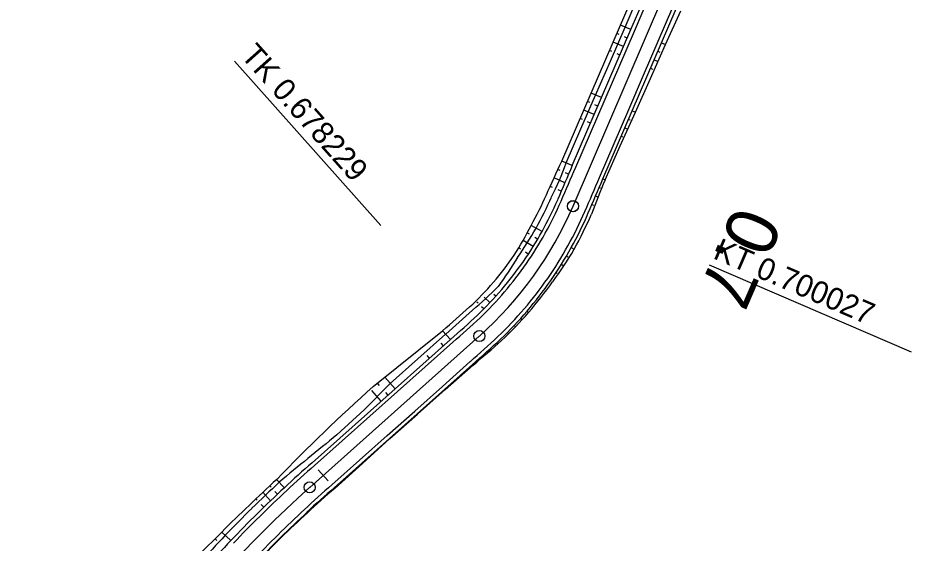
# Model space of a CAD drawing. Extents: x -481645 to -478728, y -1113199 to -1110710.
# Drawn here: x -480192.1 to -480071.5, y -1112507.2 to -1112436.3 of the extents above; entities that cross this region are included whole.
import ezdxf

# ---------------------------------------------------------------- set-up
doc = ezdxf.new("R2010")
doc.units = 0
for name, color, linetype in [('Vrstva 52', 7, 'Continuous'), ('Vrstva 53', 7, 'Continuous'), ('Vrstva 54', 7, 'Continuous'), ('Vrstva 55', 7, 'Continuous'), ('Vrstva 56', 7, 'Continuous'), ('Vrstva 57', 7, 'Continuous'), ('Vrstva 58', 7, 'Continuous'), ('Vrstva 59', 7, 'Continuous'), ('Vrstva 60', 7, 'Continuous'), ('Vrstva 61', 7, 'Continuous'), ('Vrstva 62', 7, 'Continuous')]:
    doc.layers.add(name, color=color, linetype=linetype)

msp = doc.modelspace()

# ---------------------------------------------------------------- linework, layer by layer
at = {"layer": 'Vrstva 52'}
for p, q in [((-480117.12, -1112461.7), (-480076.44, -1112367.31)), ((-480152.67, -1112499.65), (-480129.77, -1112479.24))]:
    msp.add_line(p, q, dxfattribs=at)
for centre, radius, start, end in [((-480163.03, -1112441.91), 50, 311.7077, 336.6864), ((-480052.87, -1112611.63), 150, 131.7077, 158.1186)]:
    msp.add_arc(centre, radius, start, end, dxfattribs=at)
at = {"layer": 'Vrstva 53'}
for p, q in [((-480110.71, -1112437.27), (-480108.72, -1112432.68)), ((-480104.62, -1112439.89), (-480102.58, -1112435.33)), ((-480112.69, -1112441.86), (-480110.71, -1112437.27)), ((-480106.66, -1112444.46), (-480104.62, -1112439.89)), ((-480114.68, -1112446.45), (-480112.69, -1112441.86)), ((-480108.7, -1112449.02), (-480106.66, -1112444.46)), ((-480116.66, -1112451.04), (-480114.68, -1112446.45)), ((-480110.75, -1112453.58), (-480108.7, -1112449.02)), ((-480118.65, -1112455.63), (-480116.66, -1112451.04)), ((-480112.8, -1112458.15), (-480110.75, -1112453.58)), ((-480144.1, -1112486.04), (-480134.74, -1112478.51)), ((-480134.36, -1112486.45), (-480130.61, -1112483.14)), ((-480138.11, -1112489.77), (-480134.36, -1112486.45)), ((-480149, -1112492.58), (-480145.3, -1112489.21)), ((-480141.85, -1112493.08), (-480138.11, -1112489.77)), ((-480145.56, -1112496.43), (-480141.85, -1112493.08)), ((-480149.26, -1112499.79), (-480145.56, -1112496.43))]:
    msp.add_line(p, q, dxfattribs=at)
for centre, radius, start, end in [((-485943.29, -1109801.96), 6400.66, 335.461603, 335.50635), ((-473992.43, -1114890.71), 6586.07, 158.324428, 158.367956), ((-480163, -1112441.84), 46.08, 330.828, 336.5575), ((-480163.1, -1112442.04), 52.71, 331.0858, 336.8154), ((-480163.9, -1112443.35), 46.16, 327.2716, 333.005), ((-480158.18, -1112445.91), 39.98, 312.6689, 325.9265), ((-480162.22, -1112440.65), 52.65, 323.5666, 329.2985), ((-480162.71, -1112441.49), 52.54, 318.8842, 324.6141), ((-480224.17, -1112372.54), 138.66, 310.1615, 312.1723), ((-480162.75, -1112441.61), 52.5, 313.2855, 319.0153), ((-480231.26, -1112362.09), 157.43, 309.7394, 311.5913), ((-479986.79, -1112662.6), 236.47, 131.7, 136.0823), ((-480053.4, -1112612.14), 153.8, 132.4085, 134.3184), ((-480102.14, -1112556.62), 73.83, 129.667, 133.5171), ((-480055.36, -1112614.11), 153.87, 133.2838, 135.1942), ((-480053.64, -1112612.36), 147.68, 132.2735, 134.1835), ((-480057.21, -1112616.17), 154.03, 134.1648, 136.0763), ((-480052.61, -1112611.37), 147.69, 134.7368, 136.6466)]:
    msp.add_arc(centre, radius, start, end, dxfattribs=at)
at = {"layer": 'Vrstva 54'}
for p, q in [((-480110.09, -1112437.53), (-480108.1, -1112432.95)), ((-480112.08, -1112442.12), (-480110.09, -1112437.53)), ((-480114.07, -1112446.71), (-480112.08, -1112442.12)), ((-480116.06, -1112451.29), (-480114.07, -1112446.71)), ((-480118.05, -1112455.88), (-480116.06, -1112451.29)), ((-480138.05, -1112482.31), (-480134.32, -1112478.99)), ((-480141.79, -1112485.63), (-480138.05, -1112482.31)), ((-480145.3, -1112489.21), (-480141.79, -1112485.63))]:
    msp.add_line(p, q, dxfattribs=at)
for centre, radius, start, end in [((-480146.02, -1112446.49), 29.5, 331.7223, 341.4402), ((-480162.99, -1112441.83), 46.83, 330.8136, 336.5432), ((-480162.99, -1112441.83), 46.82, 325.0838, 330.8134), ((-480164.95, -1112444.59), 46.98, 323.4712, 329.2149), ((-480160.56, -1112439.48), 46.97, 309.4939, 315.2392), ((-480226.32, -1112372.95), 140.39, 310.9473, 312.9416), ((-479873.28, -1112836.63), 440.9, 128.7078, 130.0156), ((-480053.08, -1112611.83), 153.27, 132.5743, 134.4842), ((-480053.07, -1112611.84), 153.28, 134.484, 136.3939), ((-480053.07, -1112611.84), 153.29, 136.3941, 138.3039)]:
    msp.add_arc(centre, radius, start, end, dxfattribs=at)
at = {"layer": 'Vrstva 55'}
for p, q in [((-480109.3, -1112437.88), (-480107.32, -1112433.28)), ((-480105.17, -1112439.66), (-480103.19, -1112435.06)), ((-480111.28, -1112442.47), (-480109.3, -1112437.88)), ((-480107.15, -1112444.25), (-480105.17, -1112439.66)), ((-480113.26, -1112447.06), (-480111.28, -1112442.47)), ((-480109.12, -1112448.84), (-480107.15, -1112444.25)), ((-480115.24, -1112451.65), (-480113.26, -1112447.06)), ((-480111.1, -1112453.43), (-480109.12, -1112448.84)), ((-480117.22, -1112456.24), (-480115.24, -1112451.65)), ((-480113.08, -1112458.02), (-480111.1, -1112453.43)), ((-480137.41, -1112483.03), (-480133.68, -1112479.71)), ((-480141.14, -1112486.36), (-480137.41, -1112483.03)), ((-480134.42, -1112486.39), (-480130.68, -1112483.07)), ((-480144.87, -1112489.69), (-480141.14, -1112486.36)), ((-480138.15, -1112489.72), (-480134.42, -1112486.39)), ((-480148.61, -1112493.01), (-480144.87, -1112489.69)), ((-480141.88, -1112493.05), (-480138.15, -1112489.72)), ((-480152.34, -1112496.34), (-480148.61, -1112493.01)), ((-480145.61, -1112496.37), (-480141.88, -1112493.05)), ((-480149.35, -1112499.7), (-480145.61, -1112496.37))]:
    msp.add_line(p, q, dxfattribs=at)
for centre, radius, start, end in [((-471553.39, -1116149.55), 9326.29, 156.670978, 156.701689), ((-520578.16, -1095022.28), 44061.64, 336.683075, 336.689578), ((-480163.03, -1112441.91), 47.75, 330.9256, 336.6551), ((-480163.03, -1112441.91), 52.25, 330.9256, 336.6551), ((-480163.03, -1112441.91), 47.75, 325.196, 330.9255), ((-480163.03, -1112441.91), 52.25, 325.196, 330.9256), ((-480163.03, -1112441.91), 47.75, 319.4664, 325.196), ((-480163.03, -1112441.91), 52.25, 319.4664, 325.196), ((-480163.03, -1112441.91), 47.75, 313.7368, 319.4664), ((-480227.79, -1112371.71), 143.25, 311.0724, 313.0404), ((-480163.03, -1112441.91), 52.25, 313.7368, 319.4664), ((-480233.83, -1112365.03), 156.75, 311.1489, 313.0057), ((-480103.35, -1112554.6), 76.12, 130.061, 133.8537), ((-480052.87, -1112611.63), 152.25, 132.6808, 134.5906), ((-480101.83, -1112556.27), 73.88, 130.0292, 133.8782), ((-480052.87, -1112611.63), 152.25, 134.5906, 136.5005), ((-480052.87, -1112611.63), 147.75, 132.6808, 134.5906), ((-480052.87, -1112611.63), 152.25, 136.5005, 138.4103), ((-480052.87, -1112611.63), 147.75, 134.5906, 136.5005)]:
    msp.add_arc(centre, radius, start, end, dxfattribs=at)
at = {"layer": 'Vrstva 56'}
for p, q in [((-480108.84, -1112438.07), (-480106.86, -1112433.48)), ((-480105.63, -1112439.46), (-480103.65, -1112434.87)), ((-480110.82, -1112442.67), (-480108.84, -1112438.07)), ((-480107.6, -1112444.05), (-480105.63, -1112439.46)), ((-480112.8, -1112447.26), (-480110.82, -1112442.67)), ((-480109.58, -1112448.64), (-480107.6, -1112444.05)), ((-480114.78, -1112451.85), (-480112.8, -1112447.26)), ((-480111.56, -1112453.23), (-480109.58, -1112448.64)), ((-480116.76, -1112456.44), (-480114.78, -1112451.85)), ((-480113.54, -1112457.82), (-480111.56, -1112453.23)), ((-480137.08, -1112483.41), (-480133.34, -1112480.08)), ((-480134.75, -1112486.02), (-480131.02, -1112482.69)), ((-480140.81, -1112486.73), (-480137.08, -1112483.41)), ((-480138.48, -1112489.35), (-480134.75, -1112486.02)), ((-480144.54, -1112490.06), (-480140.81, -1112486.73)), ((-480148.27, -1112493.39), (-480144.54, -1112490.06)), ((-480142.21, -1112492.67), (-480138.48, -1112489.35)), ((-480152.01, -1112496.71), (-480148.27, -1112493.39)), ((-480145.95, -1112496), (-480142.21, -1112492.67)), ((-480149.68, -1112499.33), (-480145.95, -1112496))]:
    msp.add_line(p, q, dxfattribs=at)
for centre, radius, start, end in [((-481062.27, -1112051.69), 1028.5, 336.54709, 336.82558), ((-481852.02, -1111711.35), 1891.96, 336.6106, 336.76205), ((-480163.03, -1112441.91), 48.25, 330.9256, 336.6551), ((-480163.03, -1112441.91), 51.75, 330.9256, 336.6551), ((-480163.03, -1112441.91), 48.25, 325.196, 330.9255), ((-480163.03, -1112441.91), 51.75, 325.196, 330.9256), ((-480163.03, -1112441.91), 48.25, 319.4664, 325.196), ((-480163.03, -1112441.91), 51.75, 319.4664, 325.196), ((-480163.03, -1112441.91), 48.25, 313.7368, 319.4664), ((-480163.03, -1112441.91), 51.75, 313.7368, 319.4664), ((-480228.46, -1112370.97), 144.75, 311.0815, 313.0361), ((-480233.16, -1112365.78), 155.25, 311.141, 313.0091), ((-480103.18, -1112554.79), 75.88, 130.0576, 133.8563), ((-480102, -1112556.08), 74.12, 130.0329, 133.8754), ((-480052.87, -1112611.63), 151.75, 132.6808, 134.5906), ((-480052.87, -1112611.63), 148.25, 132.6808, 134.5906), ((-480052.87, -1112611.63), 151.75, 134.5906, 136.5005), ((-480052.87, -1112611.63), 148.25, 134.5906, 136.5005)]:
    msp.add_arc(centre, radius, start, end, dxfattribs=at)
at = {"layer": 'Vrstva 57'}
for p, q in [((-480108.84, -1112438.07), (-480106.86, -1112433.48)), ((-480105.63, -1112439.46), (-480103.65, -1112434.87)), ((-480110.82, -1112442.67), (-480108.84, -1112438.07)), ((-480107.6, -1112444.05), (-480105.63, -1112439.46)), ((-480112.8, -1112447.26), (-480110.82, -1112442.67)), ((-480109.58, -1112448.64), (-480107.6, -1112444.05)), ((-480114.78, -1112451.85), (-480112.8, -1112447.26)), ((-480111.56, -1112453.23), (-480109.58, -1112448.64)), ((-480116.76, -1112456.44), (-480114.78, -1112451.85)), ((-480113.54, -1112457.82), (-480111.56, -1112453.23)), ((-480137.08, -1112483.41), (-480133.34, -1112480.08)), ((-480134.75, -1112486.02), (-480131.02, -1112482.69)), ((-480140.81, -1112486.73), (-480137.08, -1112483.41)), ((-480138.48, -1112489.35), (-480134.75, -1112486.02)), ((-480144.54, -1112490.06), (-480140.81, -1112486.73)), ((-480148.27, -1112493.39), (-480144.54, -1112490.06)), ((-480142.21, -1112492.67), (-480138.48, -1112489.35)), ((-480152.01, -1112496.71), (-480148.27, -1112493.39)), ((-480145.95, -1112496), (-480142.21, -1112492.67)), ((-480149.68, -1112499.33), (-480145.95, -1112496))]:
    msp.add_line(p, q, dxfattribs=at)
for centre, radius, start, end in [((-481062.27, -1112051.69), 1028.5, 336.54709, 336.82558), ((-481852.02, -1111711.35), 1891.96, 336.6106, 336.76205), ((-480163.03, -1112441.91), 48.25, 330.9256, 336.6551), ((-480163.03, -1112441.91), 51.75, 330.9256, 336.6551), ((-480163.03, -1112441.91), 48.25, 325.196, 330.9255), ((-480163.03, -1112441.91), 51.75, 325.196, 330.9256), ((-480163.03, -1112441.91), 48.25, 319.4664, 325.196), ((-480163.03, -1112441.91), 51.75, 319.4664, 325.196), ((-480163.03, -1112441.91), 48.25, 313.7368, 319.4664), ((-480163.03, -1112441.91), 51.75, 313.7368, 319.4664), ((-480228.46, -1112370.97), 144.75, 311.0815, 313.0361), ((-480233.16, -1112365.78), 155.25, 311.141, 313.0091), ((-480103.18, -1112554.79), 75.88, 130.0576, 133.8563), ((-480102, -1112556.08), 74.12, 130.0329, 133.8754), ((-480052.87, -1112611.63), 151.75, 132.6808, 134.5906), ((-480052.87, -1112611.63), 148.25, 132.6808, 134.5906), ((-480052.87, -1112611.63), 151.75, 134.5906, 136.5005), ((-480052.87, -1112611.63), 148.25, 134.5906, 136.5005)]:
    msp.add_arc(centre, radius, start, end, dxfattribs=at)
at = {"layer": 'Vrstva 58'}
msp.add_line((-480150.18, -1112498.77), (-480151.51, -1112497.27), dxfattribs=at)
at = {"layer": 'Vrstva 59'}
for p, q in [((-480162.84, -1112442.14), (-480143.08, -1112464.31)), ((-480098.75, -1112469.61), (-480071.48, -1112481.37))]:
    msp.add_line(p, q, dxfattribs=at)
for centre in [(-480117.12, -1112461.7), (-480129.77, -1112479.24), (-480152.67, -1112499.65)]:
    msp.add_circle(centre, 0.75, dxfattribs=at)
at = {"layer": 'Vrstva 60'}
msp.add_circle((-480117.13, -1112461.72), 0.75, dxfattribs=at)
at = {"layer": 'Vrstva 61'}
for p, q in [((-480109.3, -1112437.88), (-480110.71, -1112437.27)), ((-480110.9, -1112438.55), (-480111.2, -1112438.42)), ((-480109.79, -1112439.02), (-480110.19, -1112438.85)), ((-480110.29, -1112440.17), (-480111.7, -1112439.56)), ((-480111.89, -1112440.84), (-480112.2, -1112440.71)), ((-480110.78, -1112441.32), (-480111.18, -1112441.15)), ((-480113.26, -1112447.06), (-480114.68, -1112446.45)), ((-480114.87, -1112447.72), (-480115.17, -1112447.59)), ((-480114.25, -1112449.35), (-480115.67, -1112448.74)), ((-480113.75, -1112448.21), (-480114.16, -1112448.03)), ((-480115.86, -1112450.02), (-480116.17, -1112449.89)), ((-480114.74, -1112450.5), (-480115.15, -1112450.32)), ((-480117.22, -1112456.24), (-480118.65, -1112455.63)), ((-480118.85, -1112456.9), (-480119.17, -1112456.76)), ((-480117.71, -1112457.39), (-480118.13, -1112457.21)), ((-480118.21, -1112458.54), (-480119.68, -1112457.9)), ((-480119.87, -1112459.18), (-480120.2, -1112459.04)), ((-480118.7, -1112459.69), (-480119.12, -1112459.51)), ((-480121.3, -1112465.11), (-480122.76, -1112464.3)), ((-480121.3, -1112465.11), (-480122.76, -1112464.3)), ((-480123, -1112465.5), (-480123.3, -1112465.32)), ((-480123, -1112465.5), (-480123.3, -1112465.32)), ((-480121.9, -1112466.15), (-480122.29, -1112465.92)), ((-480121.9, -1112466.15), (-480122.29, -1112465.92)), ((-480122.51, -1112467.17), (-480123.86, -1112466.33)), ((-480122.51, -1112467.17), (-480123.86, -1112466.33)), ((-480124.19, -1112467.5), (-480124.45, -1112467.33)), ((-480124.19, -1112467.5), (-480124.45, -1112467.33)), ((-480123.16, -1112468.18), (-480123.55, -1112467.92)), ((-480123.16, -1112468.18), (-480123.55, -1112467.92)), ((-480128.34, -1112474.72), (-480129.11, -1112473.99)), ((-480127.53, -1112473.84), (-480127.79, -1112473.61)), ((-480129.94, -1112474.81), (-480130.09, -1112474.66)), ((-480129.17, -1112475.58), (-480129.48, -1112475.27)), ((-480133.68, -1112479.71), (-480134.74, -1112478.51)), ((-480134.61, -1112480.54), (-480134.93, -1112480.18)), ((-480136.48, -1112482.2), (-480136.8, -1112481.84)), ((-480141.14, -1112486.36), (-480142.54, -1112484.79)), ((-480143.23, -1112485.89), (-480143.52, -1112485.57)), ((-480143.01, -1112488.02), (-480144.3, -1112486.58)), ((-480142.08, -1112487.19), (-480142.37, -1112486.86)), ((-480157.89, -1112499.64), (-480158.07, -1112499.45)), ((-480156.09, -1112499.71), (-480157.13, -1112498.58)), ((-480157.94, -1112501.45), (-480159.01, -1112500.32)), ((-480157.02, -1112500.57), (-480157.36, -1112500.2)), ((-480159.75, -1112501.4), (-480159.93, -1112501.21)), ((-480158.85, -1112502.32), (-480159.21, -1112501.96)), ((-480163.31, -1112506.83), (-480164.53, -1112505.68)), ((-480165.19, -1112506.81), (-480165.45, -1112506.58))]:
    msp.add_line(p, q, dxfattribs=at)
at = {"layer": 'Vrstva 62'}
for p, q in [((-480105.17, -1112439.66), (-480104.62, -1112439.89)), ((-480105.66, -1112440.8), (-480105.4, -1112440.92)), ((-480105.13, -1112441.03), (-480105.13, -1112441.03)), ((-480106.16, -1112441.95), (-480105.64, -1112442.17)), ((-480106.65, -1112443.1), (-480106.4, -1112443.21)), ((-480106.15, -1112443.31), (-480106.15, -1112443.31)), ((-480109.12, -1112448.84), (-480108.7, -1112449.02)), ((-480109.62, -1112449.99), (-480109.42, -1112450.07)), ((-480109.22, -1112450.16), (-480109.22, -1112450.16)), ((-480110.11, -1112451.14), (-480109.73, -1112451.3)), ((-480110.61, -1112452.28), (-480110.42, -1112452.36)), ((-480110.24, -1112452.44), (-480110.24, -1112452.44)), ((-480113.08, -1112458.02), (-480112.8, -1112458.15)), ((-480113.58, -1112459.17), (-480113.42, -1112459.24)), ((-480113.26, -1112459.31), (-480113.26, -1112459.31)), ((-480114.07, -1112460.32), (-480113.72, -1112460.47)), ((-480114.57, -1112461.47), (-480114.37, -1112461.55)), ((-480114.18, -1112461.63), (-480114.18, -1112461.63)), ((-480117.37, -1112467.3), (-480116.96, -1112467.53)), ((-480118.7, -1112469.55), (-480118.36, -1112469.76)), ((-480118.02, -1112468.44), (-480117.83, -1112468.54)), ((-480117.65, -1112468.66), (-480117.65, -1112468.66)), ((-480119.4, -1112470.65), (-480119.25, -1112470.75)), ((-480119.1, -1112470.85), (-480119.1, -1112470.85)), ((-480123.32, -1112475.87), (-480123.12, -1112476.04)), ((-480125.07, -1112477.81), (-480124.89, -1112477.98)), ((-480124.18, -1112476.85), (-480124.09, -1112476.94)), ((-480123.99, -1112477.02), (-480123.99, -1112477.02)), ((-480125.98, -1112478.75), (-480125.9, -1112478.83)), ((-480125.81, -1112478.91), (-480125.81, -1112478.91)), ((-480131.61, -1112483.9), (-480131.58, -1112483.93)), ((-480131.55, -1112483.97), (-480131.55, -1112483.97)), ((-480130.68, -1112483.07), (-480130.61, -1112483.14)), ((-480132.55, -1112484.73), (-480132.49, -1112484.79)), ((-480133.48, -1112485.56), (-480133.45, -1112485.59)), ((-480133.43, -1112485.62), (-480133.43, -1112485.62)), ((-480138.15, -1112489.72), (-480138.11, -1112489.77)), ((-480139.08, -1112490.55), (-480139.06, -1112490.57)), ((-480139.04, -1112490.59), (-480139.04, -1112490.59)), ((-480140.95, -1112492.22), (-480140.93, -1112492.23)), ((-480140.91, -1112492.25), (-480140.91, -1112492.25)), ((-480140.01, -1112491.38), (-480139.98, -1112491.42)), ((-480146.55, -1112497.21), (-480146.52, -1112497.24)), ((-480146.49, -1112497.27), (-480146.49, -1112497.27)), ((-480145.61, -1112496.37), (-480145.56, -1112496.43)), ((-480147.48, -1112498.04), (-480147.41, -1112498.11)), ((-480148.41, -1112498.87), (-480148.38, -1112498.91)), ((-480148.34, -1112498.95), (-480148.34, -1112498.95)), ((-480153.04, -1112503.02), (-480152.97, -1112503.08)), ((-480153.94, -1112503.86), (-480153.91, -1112503.89)), ((-480153.88, -1112503.92), (-480153.88, -1112503.92)), ((-480155.72, -1112505.55), (-480155.7, -1112505.58)), ((-480155.67, -1112505.6), (-480155.67, -1112505.6)), ((-480154.83, -1112504.7), (-480154.78, -1112504.76))]:
    msp.add_line(p, q, dxfattribs=at)

# ---------------------------------------------------------------- texts
at = {"layer": 'Vrstva 59'}
for s, height, rotation, p in [('TK 0.678229', 2.999, 311.7077, (-480162.09, -1112441.47)), ('KT 0.700027', 3, 336.6864, (-480098.35, -1112468.7))]:
    msp.add_text(s, height=height, rotation=rotation, dxfattribs=at).set_placement(p)
at = {"layer": 'Vrstva 60'}
msp.add_text('0.7', height=7, rotation=246.6095, dxfattribs=at).set_placement((-480095.17, -1112461.35))

doc.saveas('drawing.dxf')
